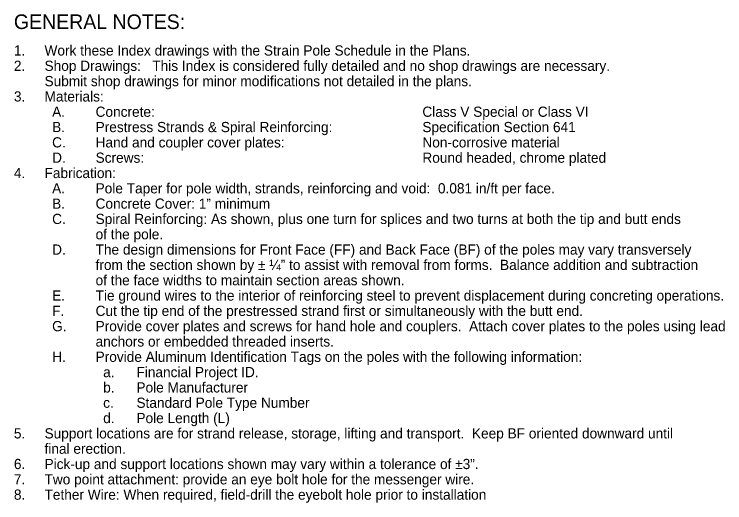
# Model space of a CAD drawing. Extents: x 10004.74 to 10009.61, y 10005.34 to 10008.69.
import ezdxf

# ---------------------------------------------------------------- set-up
doc = ezdxf.new("R2010")
doc.units = 0
doc.layers.add('DSSheetNo', color=7, linetype='Continuous')

msp = doc.modelspace()

# ---------------------------------------------------------------- texts
at = {"layer": 'DSSheetNo'}
for s, height, p in [('GENERAL NOTES:', 0.1, (10004.7334, 10008.5922)), ('1.', 0.07, (10004.7334, 10008.4102)), ('Work these Index drawings with the Strain Pole Schedule in the Plans.', 0.07, (10004.9434, 10008.4102)), ('2.', 0.07, (10004.7334, 10008.3052)), ('Shop Drawings:   This Index is considered fully detailed and no shop drawings are necessary. ', 0.07, (10004.9434, 10008.3052)), ('Submit shop drawings for minor modifications not detailed in the plans.  ', 0.07, (10004.9434, 10008.2002)), ('3.', 0.07, (10004.7334, 10008.0952)), ('Materials: ', 0.07, (10004.9434, 10008.0952)), ('  A.', 0.07, (10004.9434, 10007.9902)), ('Concrete:', 0.07, (10005.2934, 10007.9902)), ('Class V Special or Class VI', 0.07, (10007.5334, 10007.9902)), ('  B.', 0.07, (10004.9434, 10007.8852)), ('Prestress Strands & Spiral Reinforcing:', 0.07, (10005.2934, 10007.8852)), ('Specification Section 641', 0.07, (10007.5334, 10007.8852)), ('Hand and coupler cover plates:', 0.07, (10005.2934, 10007.7802)), ('Non-corrosive material', 0.07, (10007.5334, 10007.7802)), ('  C.', 0.07, (10004.9434, 10007.7802)), ('  D.', 0.07, (10004.9434, 10007.6752)), ('Screws:', 0.07, (10005.2934, 10007.6752)), ('Round headed, chrome plated ', 0.07, (10007.5334, 10007.6752)), ('4.', 0.07, (10004.7334, 10007.5702)), ('Fabrication:', 0.07, (10004.9434, 10007.5702)), ('  A.', 0.07, (10004.9434, 10007.4652)), ('Pole Taper for pole width, strands, reinforcing and void:  0.081 in/ft per face.', 0.07, (10005.2934, 10007.4652)), ('  B.', 0.07, (10004.9434, 10007.3602)), ('Concrete Cover: 1” minimum', 0.07, (10005.2934, 10007.3602)), ('  C.', 0.07, (10004.9434, 10007.2552)), ('Spiral Reinforcing: As shown, plus one turn for splices and two turns at both the tip and butt ends ', 0.07, (10005.2934, 10007.2552)), ('of the pole.', 0.07, (10005.2934, 10007.1502)), ('  D.', 0.07, (10004.9434, 10007.0452)), ('The design dimensions for Front Face (FF) and Back Face (BF) of the poles may vary transversely ', 0.07, (10005.2934, 10007.0452)), ('from the section shown by ± ¼” to assist with removal from forms.  Balance addition and subtraction ', 0.07, (10005.2934, 10006.9402)), ('of the face widths to maintain section areas shown.', 0.07, (10005.2934, 10006.8352)), ('  E.', 0.07, (10004.9434, 10006.7302)), ('Tie ground wires to the interior of reinforcing steel to prevent displacement during concreting operations.', 0.07, (10005.2934, 10006.7302)), ('  F.', 0.07, (10004.9434, 10006.6252)), ('Cut the tip end of the prestressed strand first or simultaneously with the butt end.', 0.07, (10005.2934, 10006.6252)), ('  G.', 0.07, (10004.9434, 10006.5202)), ('Provide cover plates and screws for hand hole and couplers.  Attach cover plates to the poles using lead ', 0.07, (10005.2934, 10006.5202)), ('anchors or embedded threaded inserts.  ', 0.07, (10005.2934, 10006.4152)), ('  H.', 0.07, (10004.9434, 10006.3102)), ('Provide Aluminum Identification Tags on the poles with the following information:', 0.07, (10005.2934, 10006.3102)), ('  a.', 0.07, (10005.2934, 10006.2052)), ('Financial Project ID.', 0.07, (10005.5734, 10006.2052)), ('  b.', 0.07, (10005.2934, 10006.1002)), ('Pole Manufacturer', 0.07, (10005.5734, 10006.1002)), ('  c.', 0.07, (10005.2934, 10005.9952)), ('Standard Pole Type Number', 0.07, (10005.5734, 10005.9952)), ('  d.', 0.07, (10005.2934, 10005.8902)), ('Pole Length (L)', 0.07, (10005.5734, 10005.8902)), ('5.', 0.07, (10004.7334, 10005.7852)), ('Support locations are for strand release, storage, lifting and transport.  Keep BF oriented downward until ', 0.07, (10004.9434, 10005.7852)), ('final erection.', 0.07, (10004.9434, 10005.6802)), ('6.', 0.07, (10004.7334, 10005.5752)), ('Pick-up and support locations shown may vary within a tolerance of ±3”.', 0.07, (10004.9434, 10005.5752)), ('7.', 0.07, (10004.7334, 10005.4702)), ('Two point attachment: provide an eye bolt hole for the messenger wire.', 0.07, (10004.9434, 10005.4702)), ('8.', 0.07, (10004.7334, 10005.3652)), ('Tether Wire: When required, field-drill the eyebolt hole prior to installation', 0.07, (10004.9434, 10005.3652))]:
    msp.add_text(s, height=height, dxfattribs=at).set_placement(p)

doc.saveas('drawing.dxf')
